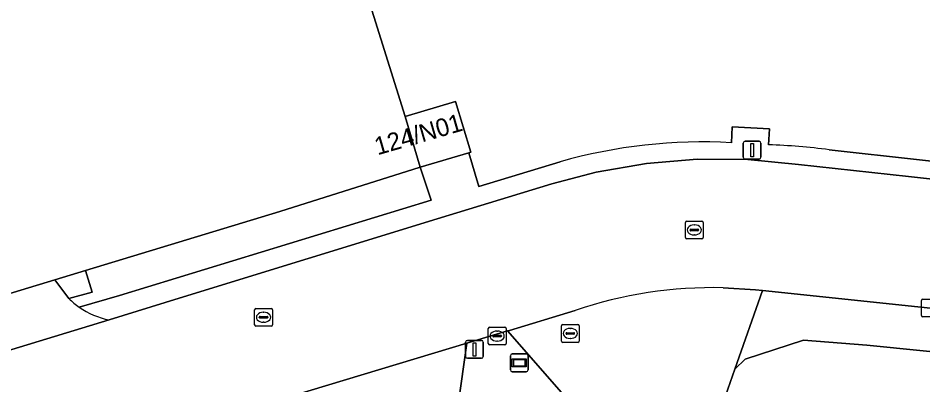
# Model space of a CAD drawing. Extents: x 161385 to 162589, y 388479 to 389756.
# Drawn here: x 162123.4 to 162174.2, y 388685.1 to 388705.7 of the extents above; entities that cross this region are included whole.
import ezdxf

# ---------------------------------------------------------------- set-up
doc = ezdxf.new("R2010")
doc.units = 0
for name, color, linetype in [('IMGEO_Afsluitpaal', 7, 'Continuous'), ('IMGEO_Brandkraan', 7, 'Continuous'), ('IMGEO_Erf', 7, 'Continuous'), ('IMGEO_Grasland_overig', 7, 'Continuous'), ('IMGEO_Groenvoorziening', 7, 'Continuous'), ('IMGEO_Hek', 7, 'Continuous'), ('IMGEO_Kolk', 7, 'Continuous'), ('IMGEO_Lichtmast', 7, 'Continuous'), ('IMGEO_Pand', 7, 'Continuous'), ('IMGEO_Pand_nummerreeks', 7, 'Continuous'), ('IMGEO_Parkeervlak_open', 7, 'Continuous'), ('IMGEO_Rijbaan_lokaal_gesloten', 7, 'Continuous'), ('IMGEO_Rijbaan_lokaal_open', 7, 'Continuous'), ('IMGEO_Rioolput', 7, 'Continuous'), ('IMGEO_Verklikker', 7, 'Continuous'), ('IMGEO_Voetpad_open', 7, 'Continuous')]:
    doc.layers.add(name, color=color, linetype=linetype)

msp = doc.modelspace()

# ---------------------------------------------------------------- linework, layer by layer
at = {"layer": 'IMGEO_Afsluitpaal'}
for p, q in [((162148.528, 388686.711), (162148.528, 388687.511)), ((162148.528, 388687.511), (162148.528, 388686.711)), ((162148.628, 388687.611), (162149.418, 388687.611)), ((162149.418, 388687.611), (162148.628, 388687.611)), ((162149.518, 388687.511), (162149.518, 388686.711)), ((162149.518, 388686.711), (162149.518, 388687.511)), ((162149.418, 388686.611), (162148.628, 388686.611)), ((162148.628, 388686.611), (162149.418, 388686.611))]:
    msp.add_line(p, q, dxfattribs=at)
msp.add_lwpolyline([(162148.948, 388687.486), (162149.098, 388687.486), (162149.098, 388686.736), (162148.948, 388686.736), (162148.948, 388687.486)], dxfattribs=at)
for centre, start, end in [((162148.628, 388687.511), 90, 180), ((162148.628, 388687.511), 90, 180), ((162149.418, 388687.511), 0, 90), ((162149.418, 388687.511), 360, 90), ((162148.628, 388686.711), 180, 270), ((162148.628, 388686.711), 180, 270), ((162149.418, 388686.711), 270, 0), ((162149.418, 388686.711), 270, 0)]:
    msp.add_arc(centre, 0.1, start, end, dxfattribs=at)
at = {"layer": 'IMGEO_Brandkraan'}
for p, q in [((162153.903, 388687.578), (162153.903, 388688.43)), ((162153.978, 388688.504), (162154.83, 388688.504)), ((162154.391, 388688.284), (162154.416, 388688.284)), ((162154.904, 388688.43), (162154.904, 388687.578)), ((162154.162, 388687.998), (162154.162, 388688.01)), ((162154.6, 388687.961), (162154.202, 388687.961)), ((162154.205, 388688.047), (162154.603, 388688.047)), ((162154.414, 388687.724), (162154.389, 388687.724)), ((162154.646, 388688.01), (162154.646, 388687.998)), ((162154.83, 388687.504), (162153.978, 388687.504))]:
    msp.add_line(p, q, dxfattribs=at)
for points in [[(162153.903, 388687.578), (162153.903, 388688.43)], [(162153.978, 388688.504), (162154.83, 388688.504)], [(162154.904, 388688.43), (162154.904, 388687.578)], [(162154.83, 388687.504), (162153.978, 388687.504)]]:
    msp.add_lwpolyline(points, dxfattribs=at)
for centre, radius, start, end in [((162153.98, 388688.428), 0.0765, 91.552, 178.448), ((162153.98, 388688.428), 0.0765, 91.552, 178.448), ((162154.828, 388688.428), 0.0765, 1.552, 88.448), ((162154.828, 388688.428), 0.0765, 1.552, 88.448), ((162154.202, 388688.007), 0.0403, 85.8775, 175.7526), ((162154.199, 388687.997), 0.0366, 178.938, 274.7102), ((162154.603, 388688.004), 0.043, 264.8664, 352.4533), ((162154.607, 388688.009), 0.0386, 1.7309, 96.639), ((162153.98, 388687.58), 0.0765, 181.552, 268.448), ((162153.98, 388687.58), 0.0765, 181.552, 268.448), ((162154.828, 388687.58), 0.0765, 271.552, 358.448), ((162154.828, 388687.58), 0.0765, 271.552, 358.448)]:
    msp.add_arc(centre, radius, start, end, dxfattribs=at)
for centre, major_axis, ratio, start_param, end_param in [((162154.39, 388688.004), (-0.387, 0.002), 0.722429, 4.712389, 7.853982), ((162154.415, 388688.004), (-0.39, 0.002), 0.717154, 1.570796, 4.712389)]:
    msp.add_ellipse(centre, major_axis=major_axis, ratio=ratio, start_param=start_param, end_param=end_param, dxfattribs=at)
at = {"layer": 'IMGEO_Erf'}
msp.add_lwpolyline([(162073.83, 388675.414), (162119.716, 388689.275), (162125.464, 388691.019), (162127.177, 388691.539), (162138.096, 388694.852), (162145.978, 388697.348), (162145.128, 388700.187), (162142.881, 388707.39), (162141.446, 388708.493), (162132.45, 388715.408), (162113.232, 388730.178), (162106.287, 388745.331), (162058.659, 388727.729)], dxfattribs=at)
at = {"layer": 'IMGEO_Grasland_overig'}
msp.add_lwpolyline([(162150.878, 388688.147), (162148.594, 388687.457), (162147.816, 388681.864), (162154.062, 388683.782), (162154.569, 388683.938)], close=True, dxfattribs=at)
at = {"layer": 'IMGEO_Groenvoorziening'}
for points in [[(162122.012, 388811.944), (162107.264, 388745.692), (162109.783, 388742.663), (162114.251, 388745.986), (162127.039, 388741.711), (162124.438, 388730.944), (162136.136, 388738.669), (162142.841, 388736.421), (162141.446, 388708.493), (162142.881, 388707.39), (162145.128, 388700.187), (162147.958, 388701.034), (162148.819, 388698.191), (162148.704, 388698.157), (162149.26, 388696.257), (162153.828, 388697.645)], [(162168.937, 388698.323), (162184.152, 388696.632), (162185.097, 388697.352), (162185.266, 388700.364), (162186.329, 388700.295), (162186.802, 388723.126), (162187.239, 388731.997), (162188.536, 388741.532), (162190.109, 388750), (162191.97, 388758.076), (162195.928, 388774.095)], [(162163.455, 388698.718), (162163.501, 388699.614), (162165.591, 388699.502), (162165.54, 388698.604)], [(162146.586, 388695.49), (162145.978, 388697.348), (162138.096, 388694.852), (162127.177, 388691.539), (162127.549, 388690.328), (162126.255, 388689.96)], [(162126.835, 388689.477), (162129.084, 388690.144), (162146.586, 388695.49)], [(162174.63, 388689.431), (162165.201, 388690.414), (162163.648, 388686.001), (162164.223, 388686.562), (162167.504, 388687.618), (162171.048, 388687.354), (162180.363, 388686.411)]]:
    msp.add_lwpolyline(points, dxfattribs=at)
for points in [[(162125.464, 388691.019), (162126.255, 388689.96), (162127.549, 388690.328), (162127.177, 388691.539)], [(162164.533, 388675.08), (162172.104, 388668.423), (162176.667, 388666.349), (162179.722, 388665.557), (162182.852, 388665.708), (162186.133, 388667.782), (162187.189, 388670.082), (162187.264, 388671.779), (162185.869, 388673.476), (162185.303, 388675.776), (162185.228, 388678.454), (162182.776, 388684.676), (162180.363, 388686.411), (162171.048, 388687.354), (162167.504, 388687.618), (162164.223, 388686.562), (162163.648, 388686.001), (162162.196, 388681.874)]]:
    msp.add_lwpolyline(points, close=True, dxfattribs=at)
for centre, radius, start, end in [((162161.799, 388669.856), 28.91, 86.7155, 106.0041), ((162164.47, 388664.997), 33.624, 82.3658, 88.1767), ((162129.387, 388693.131), 4.457, 225.357, 235.0707)]:
    msp.add_arc(centre, radius, start, end, dxfattribs=at)
at = {"layer": 'IMGEO_Hek'}
for points in [[(162145.128, 388700.187), (162142.881, 388707.39)], [(162127.177, 388691.539), (162138.096, 388694.852), (162145.978, 388697.348)], [(162125.464, 388691.019), (162127.177, 388691.539)], [(162119.716, 388689.275), (162125.464, 388691.019)]]:
    msp.add_lwpolyline(points, dxfattribs=at)
at = {"layer": 'IMGEO_Kolk'}
for p, q in [((162174.129, 388689.004), (162174.129, 388689.856)), ((162174.204, 388689.93), (162175.056, 388689.93)), ((162175.056, 388688.93), (162174.204, 388688.93)), ((162149.798, 388687.431), (162149.798, 388688.283)), ((162149.873, 388688.357), (162150.725, 388688.357)), ((162150.799, 388688.283), (162150.799, 388687.431)), ((162150.057, 388687.851), (162150.057, 388687.863)), ((162150.495, 388687.814), (162150.097, 388687.814)), ((162150.1, 388687.9), (162150.498, 388687.9)), ((162150.286, 388688.137), (162150.311, 388688.137)), ((162150.541, 388687.863), (162150.541, 388687.851)), ((162150.725, 388687.357), (162149.873, 388687.357)), ((162150.309, 388687.577), (162150.284, 388687.577))]:
    msp.add_line(p, q, dxfattribs=at)
for points in [[(162174.129, 388689.004), (162174.129, 388689.856)], [(162174.204, 388689.93), (162175.056, 388689.93)], [(162175.056, 388688.93), (162174.204, 388688.93)], [(162149.798, 388687.431), (162149.798, 388688.283)], [(162149.873, 388688.357), (162150.725, 388688.357)], [(162150.799, 388688.283), (162150.799, 388687.431)], [(162150.725, 388687.357), (162149.873, 388687.357)]]:
    msp.add_lwpolyline(points, dxfattribs=at)
for centre, radius, start, end in [((162174.206, 388689.854), 0.0765, 91.552, 178.448), ((162174.206, 388689.854), 0.0765, 91.552, 178.448), ((162174.206, 388689.006), 0.0765, 181.552, 268.448), ((162174.206, 388689.006), 0.0765, 181.552, 268.448), ((162149.875, 388688.281), 0.0765, 91.552, 178.448), ((162149.875, 388688.281), 0.0765, 91.552, 178.448), ((162150.723, 388688.281), 0.0765, 1.552, 88.448), ((162150.723, 388688.281), 0.0765, 1.552, 88.448), ((162150.097, 388687.86), 0.0403, 85.8775, 175.7526), ((162150.094, 388687.85), 0.0366, 178.938, 274.7102), ((162150.498, 388687.857), 0.043, 264.8664, 352.4533), ((162150.502, 388687.862), 0.0386, 1.7309, 96.639), ((162149.875, 388687.433), 0.0765, 181.552, 268.448), ((162149.875, 388687.433), 0.0765, 181.552, 268.448), ((162150.723, 388687.433), 0.0765, 271.552, 358.448), ((162150.723, 388687.433), 0.0765, 271.552, 358.448)]:
    msp.add_arc(centre, radius, start, end, dxfattribs=at)
for centre, major_axis, ratio, start_param, end_param in [((162150.285, 388687.857), (-0.387, 0.002), 0.722429, 4.712389, 7.853982), ((162150.31, 388687.857), (-0.39, 0.002), 0.717154, 1.570796, 4.712389)]:
    msp.add_ellipse(centre, major_axis=major_axis, ratio=ratio, start_param=start_param, end_param=end_param, dxfattribs=at)
at = {"layer": 'IMGEO_Lichtmast'}
for p, q in [((162164.115, 388697.902), (162164.115, 388698.702)), ((162164.115, 388698.702), (162164.115, 388697.902)), ((162164.215, 388698.802), (162165.005, 388698.802)), ((162165.005, 388698.802), (162164.215, 388698.802)), ((162165.105, 388698.702), (162165.105, 388697.902)), ((162165.105, 388697.902), (162165.105, 388698.702)), ((162165.005, 388697.802), (162164.215, 388697.802)), ((162164.215, 388697.802), (162165.005, 388697.802))]:
    msp.add_line(p, q, dxfattribs=at)
msp.add_lwpolyline([(162164.535, 388698.677), (162164.685, 388698.677), (162164.685, 388697.927), (162164.535, 388697.927), (162164.535, 388698.677)], dxfattribs=at)
for centre, start, end in [((162164.215, 388698.702), 90, 180), ((162164.215, 388698.702), 90, 180), ((162165.005, 388698.702), 0, 90), ((162165.005, 388698.702), 360, 90), ((162164.215, 388697.902), 180, 270), ((162164.215, 388697.902), 180, 270), ((162165.005, 388697.902), 270, 0), ((162165.005, 388697.902), 270, 0)]:
    msp.add_arc(centre, 0.1, start, end, dxfattribs=at)
at = {"layer": 'IMGEO_Pand'}
msp.add_lwpolyline([(162147.958, 388701.034), (162145.128, 388700.187), (162145.978, 388697.348), (162148.704, 388698.157), (162148.819, 388698.191)], close=True, dxfattribs=at)
at = {"layer": 'IMGEO_Parkeervlak_open'}
msp.add_lwpolyline([(162154.062, 388683.782), (162147.816, 388681.864), (162148.594, 388687.457), (162136.877, 388683.921), (162140.678, 388679.7), (162131.629, 388676.947), (162130.147, 388681.874), (162125.447, 388680.443), (162126.95, 388675.635), (162123.324, 388674.486), (162119.516, 388673.292), (162120.808, 388668.96), (162121.761, 388669.26), (162122.396, 388667.213), (162126.251, 388668.378), (162126.345, 388668.077), (162139.153, 388671.976), (162156.404, 388677.209)], close=True, dxfattribs=at)
at = {"layer": 'IMGEO_Rijbaan_lokaal_gesloten'}
for points in [[(162184.144, 388695.622), (162173.399, 388696.814), (162172.37, 388696.928), (162167.215, 388697.5), (162164.374, 388697.772), (162161.52, 388697.79), (162158.676, 388697.553), (162155.864, 388697.062), (162153.363, 388696.402), (162146.927, 388694.447), (162132.447, 388689.985), (162128.516, 388688.763), (162118, 388685.568)], [(162162.995, 388690.57), (162164.811, 388690.455), (162165.201, 388690.414), (162174.63, 388689.431), (162183.657, 388688.405), (162190.731, 388687.591), (162191.691, 388687.487), (162192.948, 388687.248), (162200.409, 388686.41), (162212.852, 388685.186), (162234.573, 388682.697), (162256.569, 388680.26), (162277.429, 388677.907), (162297.925, 388675.602), (162319.739, 388673.126), (162319.871, 388673.113), (162320.835, 388672.971), (162352.961, 388669.418)], [(162121.849, 388679.347), (162125.447, 388680.443), (162130.147, 388681.874), (162135.921, 388683.632), (162136.877, 388683.921), (162148.594, 388687.457), (162150.878, 388688.147), (162150.982, 388688.178), (162154.674, 388689.292)]]:
    msp.add_lwpolyline(points, dxfattribs=at)
msp.add_arc((162162.399, 388666.721), 23.856, 88.5689, 108.8944, dxfattribs=at)
at = {"layer": 'IMGEO_Rijbaan_lokaal_open'}
msp.add_lwpolyline([(162154.674, 388689.292), (162150.982, 388688.178), (162150.878, 388688.147), (162154.569, 388683.938), (162154.98, 388683.469), (162164.277, 388656.982), (162170.064, 388658.999), (162164.533, 388675.08), (162162.196, 388681.874), (162163.648, 388686.001), (162165.201, 388690.414), (162164.811, 388690.455), (162162.995, 388690.57)], dxfattribs=at)
msp.add_arc((162162.399, 388666.721), 23.856, 88.5689, 108.8944, dxfattribs=at)
at = {"layer": 'IMGEO_Rioolput'}
for p, q in [((162160.944, 388694.32), (162161.796, 388694.32)), ((162160.869, 388693.394), (162160.869, 388694.246)), ((162161.128, 388693.814), (162161.128, 388693.826)), ((162161.566, 388693.777), (162161.168, 388693.777)), ((162161.171, 388693.863), (162161.569, 388693.863)), ((162161.357, 388694.1), (162161.382, 388694.1)), ((162161.612, 388693.826), (162161.612, 388693.814)), ((162161.87, 388694.246), (162161.87, 388693.394)), ((162161.796, 388693.32), (162160.944, 388693.32)), ((162161.38, 388693.54), (162161.355, 388693.54)), ((162136.679, 388688.488), (162136.679, 388689.34)), ((162136.754, 388689.414), (162137.606, 388689.414)), ((162137.68, 388689.34), (162137.68, 388688.488)), ((162136.938, 388688.908), (162136.938, 388688.92)), ((162137.376, 388688.871), (162136.978, 388688.871)), ((162136.981, 388688.957), (162137.379, 388688.957)), ((162137.167, 388689.194), (162137.192, 388689.194)), ((162137.422, 388688.92), (162137.422, 388688.908)), ((162137.606, 388688.414), (162136.754, 388688.414)), ((162137.19, 388688.634), (162137.165, 388688.634))]:
    msp.add_line(p, q, dxfattribs=at)
for points in [[(162160.944, 388694.32), (162161.796, 388694.32)], [(162160.869, 388693.394), (162160.869, 388694.246)], [(162161.87, 388694.246), (162161.87, 388693.394)], [(162161.796, 388693.32), (162160.944, 388693.32)], [(162136.679, 388688.488), (162136.679, 388689.34)], [(162136.754, 388689.414), (162137.606, 388689.414)], [(162137.68, 388689.34), (162137.68, 388688.488)], [(162137.606, 388688.414), (162136.754, 388688.414)]]:
    msp.add_lwpolyline(points, dxfattribs=at)
for centre, radius, start, end in [((162160.946, 388694.244), 0.0765, 91.552, 178.448), ((162160.946, 388694.244), 0.0765, 91.552, 178.448), ((162161.794, 388694.244), 0.0765, 1.552, 88.448), ((162161.794, 388694.244), 0.0765, 1.552, 88.448), ((162161.168, 388693.823), 0.0403, 85.8775, 175.7526), ((162161.165, 388693.813), 0.0366, 178.938, 274.7102), ((162161.569, 388693.82), 0.043, 264.8664, 352.4533), ((162161.573, 388693.825), 0.0386, 1.7309, 96.639), ((162160.946, 388693.396), 0.0765, 181.552, 268.448), ((162160.946, 388693.396), 0.0765, 181.552, 268.448), ((162161.794, 388693.396), 0.0765, 271.552, 358.448), ((162161.794, 388693.396), 0.0765, 271.552, 358.448), ((162136.756, 388689.338), 0.0765, 91.552, 178.448), ((162136.756, 388689.338), 0.0765, 91.552, 178.448), ((162137.604, 388689.338), 0.0765, 1.552, 88.448), ((162137.604, 388689.338), 0.0765, 1.552, 88.448), ((162136.978, 388688.917), 0.0403, 85.8775, 175.7526), ((162136.975, 388688.907), 0.0366, 178.938, 274.7102), ((162137.379, 388688.914), 0.043, 264.8664, 352.4533), ((162137.383, 388688.919), 0.0386, 1.7309, 96.639), ((162136.756, 388688.49), 0.0765, 181.552, 268.448), ((162136.756, 388688.49), 0.0765, 181.552, 268.448), ((162137.604, 388688.49), 0.0765, 271.552, 358.448), ((162137.604, 388688.49), 0.0765, 271.552, 358.448)]:
    msp.add_arc(centre, radius, start, end, dxfattribs=at)
for centre, major_axis, ratio, start_param, end_param in [((162161.356, 388693.82), (-0.387, 0.002), 0.722429, 4.712389, 7.853982), ((162161.381, 388693.82), (-0.39, 0.002), 0.717154, 1.570796, 4.712389), ((162137.166, 388688.914), (-0.387, 0.002), 0.722429, 4.712389, 7.853982), ((162137.191, 388688.914), (-0.39, 0.002), 0.717154, 1.570796, 4.712389)]:
    msp.add_ellipse(centre, major_axis=major_axis, ratio=ratio, start_param=start_param, end_param=end_param, dxfattribs=at)
at = {"layer": 'IMGEO_Verklikker'}
for p, q in [((162151.041, 388685.953), (162151.041, 388686.753)), ((162151.041, 388686.753), (162151.041, 388685.953)), ((162151.141, 388686.853), (162151.931, 388686.853)), ((162151.931, 388686.853), (162151.141, 388686.853)), ((162152.031, 388686.753), (162152.031, 388685.953)), ((162152.031, 388685.953), (162152.031, 388686.753)), ((162151.931, 388685.853), (162151.141, 388685.853)), ((162151.141, 388685.853), (162151.931, 388685.853))]:
    msp.add_line(p, q, dxfattribs=at)
for points in [[(162151.142, 388686.585), (162151.93, 388686.585), (162151.93, 388686.121), (162151.142, 388686.121), (162151.142, 388686.585)], [(162151.207, 388686.52), (162151.207, 388686.186), (162151.865, 388686.186), (162151.865, 388686.52), (162151.207, 388686.52)]]:
    msp.add_lwpolyline(points, dxfattribs=at)
for centre, start, end in [((162151.141, 388686.753), 90, 180), ((162151.141, 388686.753), 90, 180), ((162151.931, 388686.753), 0, 90), ((162151.931, 388686.753), 360, 90), ((162151.141, 388685.953), 180, 270), ((162151.141, 388685.953), 180, 270), ((162151.931, 388685.953), 270, 0), ((162151.931, 388685.953), 270, 0)]:
    msp.add_arc(centre, 0.1, start, end, dxfattribs=at)
at = {"layer": 'IMGEO_Voetpad_open'}
for points in [[(162165.54, 388698.604), (162165.591, 388699.502), (162163.501, 388699.614), (162163.455, 388698.718)], [(162153.828, 388697.645), (162149.26, 388696.257), (162148.704, 388698.157), (162145.978, 388697.348)], [(162184.152, 388696.632), (162168.937, 388698.323)], [(162145.978, 388697.348), (162146.586, 388695.49), (162129.084, 388690.144), (162126.835, 388689.477)], [(162128.516, 388688.763), (162132.447, 388689.985), (162146.927, 388694.447), (162153.363, 388696.402), (162155.864, 388697.062), (162158.676, 388697.553), (162161.52, 388697.79), (162164.374, 388697.772), (162167.215, 388697.5), (162172.37, 388696.928), (162173.399, 388696.814), (162184.144, 388695.622)], [(162126.255, 388689.96), (162125.464, 388691.019), (162119.716, 388689.275)], [(162118.612, 388686.058), (162118, 388685.568), (162128.516, 388688.763)]]:
    msp.add_lwpolyline(points, dxfattribs=at)
for centre, radius, start, end in [((162161.799, 388669.856), 28.91, 86.7155, 106.0041), ((162164.47, 388664.997), 33.624, 82.3658, 88.1767), ((162129.387, 388693.131), 4.457, 225.357, 235.0707), ((162129.372, 388693.113), 4.434, 235.1011, 258.8725), ((162129.372, 388693.113), 4.434, 235.1011, 258.8725)]:
    msp.add_arc(centre, radius, start, end, dxfattribs=at)

# ---------------------------------------------------------------- texts
at = {"layer": 'IMGEO_Pand_nummerreeks'}
msp.add_text('124/N01', height=1, rotation=16.1746, dxfattribs=at).set_placement((162143.58, 388698.011))

doc.saveas('drawing.dxf')
